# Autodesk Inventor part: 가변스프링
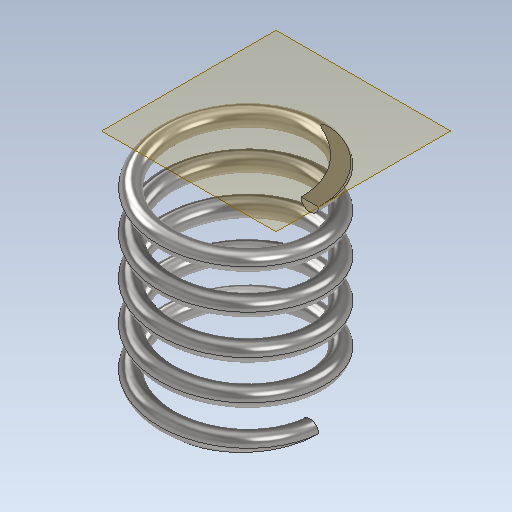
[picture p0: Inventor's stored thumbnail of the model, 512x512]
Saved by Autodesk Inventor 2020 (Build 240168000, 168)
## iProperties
Created: 2022-09
Part Number: 가변스프링
Material: 스테인레스 스틸
Document SubType Name: Modeling
Designer: 101-13
Mass: 6.58485 g
Surface Area: 16.7367 cm^2
Volume: 0.823106 cm^3
Density: 8 g/cm^3
Appearance: 반연마
Author: 101-13
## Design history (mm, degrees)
node "작업 평면1"
sketch "스케치1"
  geometry: L1 (-1.9, 22.5)-(11.4, 22.5) reference; L2 (0, 0)-(8.5, 0); L3 (8.5, 0)-(8.5, 21.871); L4 (8.5, 21.871)-(0, 21.871); L5 (0, 21.871)-(0, 0); C1 r 1 at (8.5, 0)
  constraints: 8 end point, 2 parallel, 1 centre point, 1 coincident, 1 horizontal, 1 perpendicular
  dimensions: "d1" = 22.5 distance from line of L1 L2.start (derived); "d2" = 2 diameter of C1; "d3" = 17 diameter of L3 L5
feature "코일1" sketch "스케치1" pitch "d4" = 10; turns "d6" = 5; dims "d5" = 22.5 (= HEIGHT), "d7" = 0, angle "d8" = 90 deg, angle "d9" = 90 deg, "d10" = 0, "d11" = 0
feature "분할1"
feature "분할2"
node "솔리드1"
other parameters: "HEIGHT" = 22.5 (= d1) [user parameter; used in 1 equation term]
